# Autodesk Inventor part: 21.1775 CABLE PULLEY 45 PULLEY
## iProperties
Created: 2007-05
Part Number: 21.1775 CABLE PULLEY 45 PULLEY
Material: Steel
Document SubType Name: Modeling
Designer: Andy Moles
Mass: 113.94 g
Surface Area: 58.6818 cm^2
Volume: 14.5146 cm^3
Density: 7.85 g/cm^3
Author: Andy Moles
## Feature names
1. Revolution1
